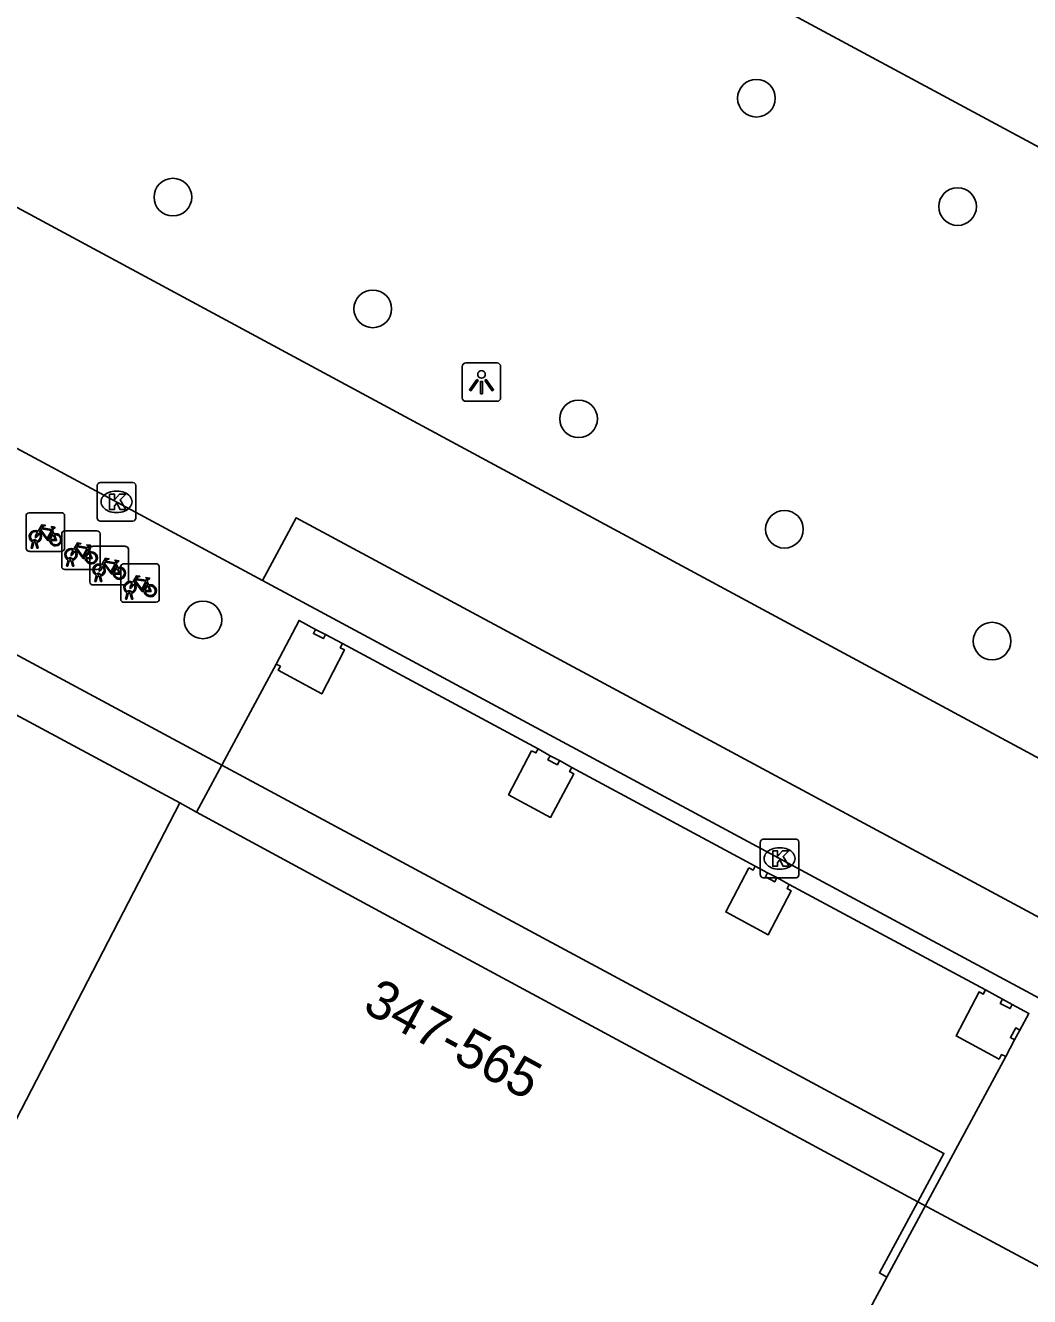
# Model space of a CAD drawing. Extents: x 159489 to 160304, y 383826 to 384530.
# Drawn here: x 159552.76 to 159578.83, y 384279.19 to 384312.2 of the extents above; entities that cross this region are included whole.
import ezdxf

# ---------------------------------------------------------------- set-up
doc = ezdxf.new("R2010")
doc.units = 0
for name, color, linetype in [('IMGEO_Boom', 7, 'Continuous'), ('IMGEO_Fietsenrek', 7, 'Continuous'), ('IMGEO_Kolk', 7, 'Continuous'), ('IMGEO_Lichtpunt', 7, 'Continuous'), ('IMGEO_Pand', 7, 'Continuous'), ('IMGEO_Pand_nummerreeks', 7, 'Continuous'), ('IMGEO_Pand_overbouw', 7, 'Continuous'), ('IMGEO_Rijbaan_lokaal_gesloten', 7, 'Continuous'), ('IMGEO_Voetgangersgebied_gesloten', 7, 'Continuous'), ('IMGEO_Voetpad_open', 7, 'Continuous')]:
    doc.layers.add(name, color=color, linetype=linetype)

msp = doc.modelspace()

# ---------------------------------------------------------------- linework, layer by layer
at = {"layer": 'IMGEO_Boom'}
for centre in [(159571.742, 384310.314), (159556.59, 384307.745), (159576.966, 384307.5), (159561.779, 384304.844), (159567.125, 384301.988), (159572.468, 384299.119), (159557.37, 384296.767), (159577.86, 384296.215)]:
    msp.add_circle(centre, 0.489, dxfattribs=at)
at = {"layer": 'IMGEO_Fietsenrek'}
for p, q in [((159552.779, 384298.622), (159552.779, 384299.463)), ((159552.779, 384299.463), (159552.779, 384298.622)), ((159552.854, 384299.547), (159553.695, 384299.547)), ((159553.695, 384299.547), (159552.854, 384299.547)), ((159553.779, 384299.472), (159553.779, 384298.631)), ((159553.779, 384298.631), (159553.779, 384299.472)), ((159553.466, 384299.096), (159553.502, 384299.001)), ((159553.777, 384299.077), (159554.618, 384299.077)), ((159554.618, 384299.077), (159553.777, 384299.077)), ((159552.906, 384298.631), (159552.945, 384298.791)), ((159552.975, 384298.779), (159552.94, 384298.631)), ((159553.017, 384298.803), (159553.016, 384298.807)), ((159553.058, 384298.631), (159553.024, 384298.773)), ((159553.048, 384298.814), (159553.049, 384298.807)), ((159553.056, 384298.777), (159553.091, 384298.631)), ((159553.702, 384298.152), (159553.702, 384298.993)), ((159553.702, 384298.993), (159553.702, 384298.152)), ((159554.702, 384299.002), (159554.702, 384298.161)), ((159554.702, 384298.161), (159554.702, 384299.002)), ((159553.704, 384298.547), (159552.863, 384298.547)), ((159552.863, 384298.547), (159553.704, 384298.547)), ((159552.94, 384298.631), (159552.906, 384298.631)), ((159553.091, 384298.631), (159553.058, 384298.631)), ((159554.389, 384298.626), (159554.425, 384298.531)), ((159554.433, 384297.752), (159554.433, 384298.593)), ((159554.433, 384298.593), (159554.433, 384297.752)), ((159554.508, 384298.677), (159555.349, 384298.677)), ((159555.349, 384298.677), (159554.508, 384298.677)), ((159555.433, 384298.602), (159555.433, 384297.761)), ((159555.433, 384297.761), (159555.433, 384298.602)), ((159554.627, 384298.077), (159553.786, 384298.077)), ((159553.786, 384298.077), (159554.627, 384298.077)), ((159553.829, 384298.161), (159553.868, 384298.321)), ((159553.863, 384298.161), (159553.829, 384298.161)), ((159553.898, 384298.309), (159553.863, 384298.161)), ((159553.94, 384298.333), (159553.939, 384298.337)), ((159553.981, 384298.161), (159553.947, 384298.303)), ((159553.971, 384298.344), (159553.972, 384298.337)), ((159553.979, 384298.307), (159554.014, 384298.161)), ((159554.014, 384298.161), (159553.981, 384298.161)), ((159555.12, 384298.226), (159555.156, 384298.131)), ((159555.234, 384297.299), (159555.234, 384298.14)), ((159555.234, 384298.14), (159555.234, 384297.299)), ((159555.309, 384298.224), (159556.15, 384298.224)), ((159556.15, 384298.224), (159555.309, 384298.224)), ((159556.234, 384298.149), (159556.234, 384297.308)), ((159556.234, 384297.308), (159556.234, 384298.149)), ((159554.56, 384297.761), (159554.599, 384297.921)), ((159554.594, 384297.761), (159554.56, 384297.761)), ((159554.629, 384297.909), (159554.594, 384297.761)), ((159554.671, 384297.933), (159554.67, 384297.937)), ((159554.712, 384297.761), (159554.678, 384297.903)), ((159554.702, 384297.944), (159554.703, 384297.937)), ((159554.71, 384297.907), (159554.745, 384297.761)), ((159554.745, 384297.761), (159554.712, 384297.761)), ((159555.921, 384297.773), (159555.957, 384297.678)), ((159555.358, 384297.677), (159554.517, 384297.677)), ((159554.517, 384297.677), (159555.358, 384297.677)), ((159555.361, 384297.308), (159555.4, 384297.468)), ((159555.43, 384297.456), (159555.395, 384297.308)), ((159555.472, 384297.48), (159555.471, 384297.484)), ((159555.513, 384297.308), (159555.479, 384297.45)), ((159555.503, 384297.491), (159555.504, 384297.484)), ((159555.511, 384297.454), (159555.546, 384297.308)), ((159556.159, 384297.224), (159555.318, 384297.224)), ((159555.318, 384297.224), (159556.159, 384297.224)), ((159555.395, 384297.308), (159555.361, 384297.308)), ((159555.546, 384297.308), (159555.513, 384297.308))]:
    msp.add_line(p, q, dxfattribs=at)
for points in [[(159553.092, 384299.073), (159553.187, 384299.237), (159553.273, 384299.223), (159553.275, 384299.214), (159553.219, 384299.203), (159553.192, 384299.158), (159553.448, 384299.117)], [(159553.388, 384298.829), (159553.338, 384298.829), (159553.147, 384299.08), (159553.128, 384299.048)], [(159553.435, 384299.092), (159553.178, 384299.133), (159553.161, 384299.104), (159553.328, 384298.884), (159553.435, 384299.092)], [(159553.483, 384298.994), (159553.453, 384299.071), (159553.344, 384298.853), (159553.387, 384298.853)], [(159553.448, 384299.117), (159553.473, 384299.166), (159553.467, 384299.17), (159553.444, 384299.174), (159553.432, 384299.181), (159553.431, 384299.184), (159553.433, 384299.189), (159553.528, 384299.174), (159553.53, 384299.164), (159553.52, 384299.151), (159553.508, 384299.145), (159553.494, 384299.151), (159553.466, 384299.096)], [(159553.113, 384299.021), (159553.061, 384298.931), (159553.021, 384298.906), (159553.022, 384298.953), (159553.077, 384299.047)], [(159553.417, 384298.853), (159553.537, 384298.852), (159553.493, 384298.966)], [(159553.513, 384298.973), (159553.568, 384298.828), (159553.418, 384298.828)], [(159554.015, 384298.603), (159554.11, 384298.767), (159554.196, 384298.753), (159554.198, 384298.744), (159554.142, 384298.733), (159554.115, 384298.688), (159554.371, 384298.647)], [(159554.036, 384298.551), (159553.984, 384298.461), (159553.944, 384298.436), (159553.945, 384298.483), (159554, 384298.577)], [(159554.311, 384298.359), (159554.261, 384298.359), (159554.07, 384298.61), (159554.051, 384298.578)], [(159554.358, 384298.622), (159554.101, 384298.663), (159554.084, 384298.634), (159554.251, 384298.414), (159554.358, 384298.622)], [(159554.406, 384298.524), (159554.376, 384298.601), (159554.267, 384298.383), (159554.31, 384298.383)], [(159554.34, 384298.383), (159554.46, 384298.382), (159554.416, 384298.496)], [(159554.436, 384298.503), (159554.491, 384298.358), (159554.341, 384298.358)], [(159554.371, 384298.647), (159554.396, 384298.696), (159554.39, 384298.7), (159554.367, 384298.704), (159554.355, 384298.711), (159554.354, 384298.714), (159554.356, 384298.719), (159554.451, 384298.704), (159554.453, 384298.694), (159554.443, 384298.681), (159554.431, 384298.675), (159554.417, 384298.681), (159554.389, 384298.626)], [(159554.767, 384298.151), (159554.715, 384298.061), (159554.675, 384298.036), (159554.676, 384298.083), (159554.731, 384298.177)], [(159554.746, 384298.203), (159554.841, 384298.367), (159554.927, 384298.353), (159554.929, 384298.344), (159554.873, 384298.333), (159554.846, 384298.288), (159555.102, 384298.247)], [(159555.042, 384297.959), (159554.992, 384297.959), (159554.801, 384298.21), (159554.782, 384298.178)], [(159555.089, 384298.222), (159554.832, 384298.263), (159554.815, 384298.234), (159554.982, 384298.014), (159555.089, 384298.222)], [(159555.137, 384298.124), (159555.107, 384298.201), (159554.998, 384297.983), (159555.041, 384297.983)], [(159555.071, 384297.983), (159555.191, 384297.982), (159555.147, 384298.096)], [(159555.167, 384298.103), (159555.222, 384297.958), (159555.072, 384297.958)], [(159555.102, 384298.247), (159555.127, 384298.296), (159555.121, 384298.3), (159555.098, 384298.304), (159555.086, 384298.311), (159555.085, 384298.314), (159555.087, 384298.319), (159555.182, 384298.304), (159555.184, 384298.294), (159555.174, 384298.281), (159555.162, 384298.275), (159555.148, 384298.281), (159555.12, 384298.226)], [(159555.547, 384297.75), (159555.642, 384297.914), (159555.728, 384297.9), (159555.73, 384297.891), (159555.674, 384297.88), (159555.647, 384297.835), (159555.903, 384297.794)], [(159555.843, 384297.506), (159555.793, 384297.506), (159555.602, 384297.757), (159555.583, 384297.725)], [(159555.89, 384297.769), (159555.633, 384297.81), (159555.616, 384297.781), (159555.783, 384297.561), (159555.89, 384297.769)], [(159555.938, 384297.671), (159555.908, 384297.748), (159555.799, 384297.53), (159555.842, 384297.53)], [(159555.903, 384297.794), (159555.928, 384297.843), (159555.922, 384297.847), (159555.899, 384297.851), (159555.887, 384297.858), (159555.886, 384297.861), (159555.888, 384297.866), (159555.983, 384297.851), (159555.985, 384297.841), (159555.975, 384297.828), (159555.963, 384297.822), (159555.949, 384297.828), (159555.921, 384297.773)], [(159555.568, 384297.698), (159555.516, 384297.608), (159555.476, 384297.583), (159555.477, 384297.63), (159555.532, 384297.724)], [(159555.872, 384297.53), (159555.992, 384297.529), (159555.948, 384297.643)], [(159555.968, 384297.65), (159556.023, 384297.505), (159555.873, 384297.505)]]:
    msp.add_lwpolyline(points, dxfattribs=at)
for centre, radius, start, end in [((159552.857, 384299.469), 0.0779, 92.4484, 184.2845), ((159552.857, 384299.469), 0.0779, 92.4484, 184.2845), ((159553.701, 384299.469), 0.0779, 2.4484, 94.2845), ((159553.701, 384299.469), 0.0779, 2.4484, 94.2845), ((159553.019, 384298.932), 0.159, 62.6766, 242.1369), ((159553.78, 384298.999), 0.0779, 92.4484, 184.2845), ((159553.78, 384298.999), 0.0779, 92.4484, 184.2845), ((159554.624, 384298.999), 0.0779, 2.4484, 94.2845), ((159554.624, 384298.999), 0.0779, 2.4484, 94.2845), ((159553.019, 384298.932), 0.129, 63.3192, 238.903), ((159552.999, 384298.803), 0.0499, 12.8025, 158.6934), ((159553.019, 384298.932), 0.159, 253.9967, 271.7867), ((159552.999, 384298.803), 0.0174, 12.8025, 163.4502), ((159553.019, 384298.932), 0.129, 253.415, 269.0204), ((159553.019, 384298.932), 0.129, 283.6043, 43.4302), ((159553.019, 384298.932), 0.159, 283.5766, 46.6042), ((159553.546, 384298.848), 0.159, 113.3408, 178.3217), ((159553.546, 384298.848), 0.159, 187.0065, 105.7708), ((159553.546, 384298.848), 0.129, 113.923, 177.9556), ((159553.546, 384298.848), 0.129, 188.6715, 104.5883), ((159552.857, 384298.625), 0.0779, 182.4484, 274.2845), ((159552.857, 384298.625), 0.0779, 182.4484, 274.2845), ((159553.701, 384298.625), 0.0779, 272.4484, 4.2845), ((159553.701, 384298.625), 0.0779, 272.4484, 4.2845), ((159553.942, 384298.462), 0.159, 62.6766, 242.1369), ((159553.942, 384298.462), 0.129, 63.3192, 238.903), ((159553.942, 384298.462), 0.129, 283.6043, 43.4302), ((159553.942, 384298.462), 0.159, 283.5766, 46.6042), ((159554.469, 384298.378), 0.159, 113.3408, 178.3217), ((159554.469, 384298.378), 0.159, 187.0065, 105.7708), ((159554.469, 384298.378), 0.129, 113.923, 177.9556), ((159554.469, 384298.378), 0.129, 188.6715, 104.5883), ((159554.511, 384298.599), 0.0779, 92.4484, 184.2845), ((159554.511, 384298.599), 0.0779, 92.4484, 184.2845), ((159555.355, 384298.599), 0.0779, 2.4484, 94.2845), ((159555.355, 384298.599), 0.0779, 2.4484, 94.2845), ((159553.78, 384298.155), 0.0779, 182.4484, 274.2845), ((159553.78, 384298.155), 0.0779, 182.4484, 274.2845), ((159553.922, 384298.333), 0.0499, 12.8025, 158.6934), ((159553.942, 384298.462), 0.159, 253.9967, 271.7867), ((159553.922, 384298.333), 0.0174, 12.8025, 163.4502), ((159553.942, 384298.462), 0.129, 253.415, 269.0204), ((159554.673, 384298.062), 0.159, 62.6766, 242.1369), ((159554.673, 384298.062), 0.129, 63.3192, 238.903), ((159554.624, 384298.155), 0.0779, 272.4484, 4.2845), ((159554.624, 384298.155), 0.0779, 272.4484, 4.2845), ((159554.673, 384298.062), 0.129, 283.6043, 43.4302), ((159554.673, 384298.062), 0.159, 283.5766, 46.6042), ((159555.2, 384297.978), 0.159, 113.3408, 178.3217), ((159555.2, 384297.978), 0.159, 187.0065, 105.7708), ((159555.2, 384297.978), 0.129, 113.923, 177.9556), ((159555.2, 384297.978), 0.129, 188.6715, 104.5883), ((159555.312, 384298.146), 0.0779, 92.4484, 184.2845), ((159555.312, 384298.146), 0.0779, 92.4484, 184.2845), ((159556.156, 384298.146), 0.0779, 2.4484, 94.2845), ((159556.156, 384298.146), 0.0779, 2.4484, 94.2845), ((159554.511, 384297.755), 0.0779, 182.4484, 274.2845), ((159554.511, 384297.755), 0.0779, 182.4484, 274.2845), ((159554.653, 384297.933), 0.0499, 12.8025, 158.6934), ((159554.673, 384298.062), 0.159, 253.9967, 271.7867), ((159554.653, 384297.933), 0.0174, 12.8025, 163.4502), ((159554.673, 384298.062), 0.129, 253.415, 269.0204), ((159555.474, 384297.609), 0.159, 62.6766, 242.1369), ((159555.355, 384297.755), 0.0779, 272.4484, 4.2845), ((159555.355, 384297.755), 0.0779, 272.4484, 4.2845), ((159555.474, 384297.609), 0.129, 63.3192, 238.903), ((159555.454, 384297.48), 0.0499, 12.8025, 158.6934), ((159555.474, 384297.609), 0.159, 253.9967, 271.7867), ((159555.454, 384297.48), 0.0174, 12.8025, 163.4502), ((159555.474, 384297.609), 0.129, 253.415, 269.0204), ((159555.474, 384297.609), 0.129, 283.6043, 43.4302), ((159555.474, 384297.609), 0.159, 283.5766, 46.6042), ((159556.001, 384297.525), 0.159, 113.3408, 178.3217), ((159556.001, 384297.525), 0.159, 187.0065, 105.7708), ((159556.001, 384297.525), 0.129, 113.923, 177.9556), ((159556.001, 384297.525), 0.129, 188.6715, 104.5883), ((159555.312, 384297.302), 0.0779, 182.4484, 274.2845), ((159555.312, 384297.302), 0.0779, 182.4484, 274.2845), ((159556.156, 384297.302), 0.0779, 272.4484, 4.2845), ((159556.156, 384297.302), 0.0779, 272.4484, 4.2845)]:
    msp.add_arc(centre, radius, start, end, dxfattribs=at)
at = {"layer": 'IMGEO_Kolk'}
for p, q in [((159554.626, 384299.407), (159554.626, 384300.259)), ((159554.701, 384300.333), (159555.553, 384300.333)), ((159555.114, 384300.113), (159555.139, 384300.113)), ((159555.627, 384300.259), (159555.627, 384299.407)), ((159555.137, 384299.553), (159555.112, 384299.553)), ((159555.553, 384299.333), (159554.701, 384299.333)), ((159571.843, 384290.145), (159571.843, 384290.997)), ((159571.918, 384291.071), (159572.77, 384291.071)), ((159572.331, 384290.851), (159572.356, 384290.851)), ((159572.844, 384290.997), (159572.844, 384290.145)), ((159572.354, 384290.291), (159572.329, 384290.291)), ((159572.77, 384290.071), (159571.918, 384290.071))]:
    msp.add_line(p, q, dxfattribs=at)
for points in [[(159554.626, 384299.407), (159554.626, 384300.259)], [(159554.701, 384300.333), (159555.553, 384300.333)], [(159555.627, 384300.259), (159555.627, 384299.407)], [(159554.947, 384300.033), (159555.07, 384300.033), (159555.07, 384299.882), (159555.2, 384300.033), (159555.364, 384300.033), (159555.218, 384299.882), (159555.371, 384299.633), (159555.219, 384299.633), (159555.134, 384299.797), (159555.07, 384299.73), (159555.07, 384299.633), (159554.947, 384299.633), (159554.947, 384300.033)], [(159555.553, 384299.333), (159554.701, 384299.333)], [(159571.843, 384290.145), (159571.843, 384290.997)], [(159571.918, 384291.071), (159572.77, 384291.071)], [(159572.844, 384290.997), (159572.844, 384290.145)], [(159572.164, 384290.771), (159572.287, 384290.771), (159572.287, 384290.62), (159572.417, 384290.771), (159572.581, 384290.771), (159572.435, 384290.62), (159572.588, 384290.371), (159572.436, 384290.371), (159572.351, 384290.535), (159572.287, 384290.468), (159572.287, 384290.371), (159572.164, 384290.371), (159572.164, 384290.771)], [(159572.77, 384290.071), (159571.918, 384290.071)]]:
    msp.add_lwpolyline(points, dxfattribs=at)
for centre, start, end in [((159554.703, 384300.257), 91.552, 178.448), ((159554.703, 384300.257), 91.552, 178.448), ((159555.551, 384300.257), 1.552, 88.448), ((159555.551, 384300.257), 1.552, 88.448), ((159554.703, 384299.409), 181.552, 268.448), ((159554.703, 384299.409), 181.552, 268.448), ((159555.551, 384299.409), 271.552, 358.448), ((159555.551, 384299.409), 271.552, 358.448), ((159571.92, 384290.995), 91.552, 178.448), ((159571.92, 384290.995), 91.552, 178.448), ((159572.768, 384290.995), 1.552, 88.448), ((159572.768, 384290.995), 1.552, 88.448), ((159571.92, 384290.147), 181.552, 268.448), ((159571.92, 384290.147), 181.552, 268.448), ((159572.768, 384290.147), 271.552, 358.448), ((159572.768, 384290.147), 271.552, 358.448)]:
    msp.add_arc(centre, 0.0765, start, end, dxfattribs=at)
for centre, major_axis, ratio, start_param, end_param in [((159555.113, 384299.833), (-0.387, 0.002), 0.722429, 4.712389, 7.853982), ((159555.138, 384299.833), (-0.39, 0.002), 0.717154, 1.570796, 4.712389), ((159572.33, 384290.571), (-0.387, 0.002), 0.722429, 4.712389, 7.853982), ((159572.355, 384290.571), (-0.39, 0.002), 0.717154, 1.570796, 4.712389)]:
    msp.add_ellipse(centre, major_axis=major_axis, ratio=ratio, start_param=start_param, end_param=end_param, dxfattribs=at)
at = {"layer": 'IMGEO_Lichtpunt'}
for p, q in [((159565.006, 384303.439), (159564.198, 384303.439)), ((159565.006, 384303.439), (159564.198, 384303.439)), ((159564.104, 384303.344), (159564.104, 384302.537)), ((159564.104, 384303.344), (159564.104, 384302.537)), ((159565.1, 384302.537), (159565.1, 384303.344)), ((159565.1, 384302.537), (159565.1, 384303.344)), ((159564.198, 384302.443), (159565.006, 384302.443)), ((159564.198, 384302.443), (159565.006, 384302.443))]:
    msp.add_line(p, q, dxfattribs=at)
for points in [[(159564.478, 384303.008), (159564.517, 384302.98), (159564.329, 384302.718), (159564.291, 384302.745), (159564.478, 384303.008)], [(159564.58, 384302.96), (159564.627, 384302.96), (159564.627, 384302.638), (159564.58, 384302.638), (159564.58, 384302.96)], [(159564.69, 384302.98), (159564.728, 384303.007), (159564.915, 384302.745), (159564.876, 384302.717), (159564.69, 384302.98)]]:
    msp.add_lwpolyline(points, dxfattribs=at)
msp.add_circle((159564.603, 384303.142), 0.0994, dxfattribs=at)
for centre, start, end in [((159564.198, 384303.344), 90, 180), ((159564.198, 384303.344), 90, 180), ((159565.006, 384303.344), 0, 90), ((159565.006, 384303.344), 0, 90), ((159564.198, 384302.537), 180, 270), ((159564.198, 384302.537), 180, 270), ((159565.006, 384302.537), 270, 0), ((159565.006, 384302.537), 270, 360)]:
    msp.add_arc(centre, 0.0946, start, end, dxfattribs=at)
at = {"layer": 'IMGEO_Pand'}
for points in [[(159527.484, 384307.756), (159556.766, 384292.015)], [(159559.382, 384295.564), (159559.275, 384295.619), (159559.868, 384296.753), (159560.296, 384296.519), (159560.239, 384296.411), (159560.498, 384296.28), (159560.556, 384296.388), (159560.994, 384296.151), (159560.936, 384296.043), (159561.044, 384295.985), (159560.456, 384294.845), (159559.324, 384295.457), (159559.382, 384295.564)], [(159565.904, 384293.366), (159566.015, 384293.31), (159566.072, 384293.416), (159566.382, 384293.24), (159566.327, 384293.131), (159566.576, 384293.004), (159566.63, 384293.113), (159566.946, 384292.937), (159566.89, 384292.829), (159566.999, 384292.769), (159566.395, 384291.637), (159565.308, 384292.224), (159565.904, 384293.366)], [(159556.766, 384292.015), (159545.068, 384269.391)], [(159556.766, 384292.015), (159557.204, 384291.777), (159563.611, 384288.299), (159575.933, 384281.657)], [(159571.543, 384290.325), (159571.654, 384290.27), (159571.711, 384290.375), (159572.031, 384290.202), (159571.975, 384290.09), (159572.218, 384289.961), (159572.274, 384290.073), (159572.594, 384289.895), (159572.536, 384289.787), (159572.645, 384289.73), (159572.049, 384288.588), (159570.947, 384289.184), (159571.543, 384290.325)], [(159577.69, 384287.156), (159578.134, 384286.918), (159578.074, 384286.808), (159578.327, 384286.674), (159578.384, 384286.782), (159578.819, 384286.547), (159578.582, 384286.113), (159578.477, 384286.17), (159578.339, 384285.92), (159578.446, 384285.864), (159578.215, 384285.424), (159578.109, 384285.479), (159578.044, 384285.36), (159576.926, 384285.964), (159577.522, 384287.106), (159577.633, 384287.05), (159577.69, 384287.156)], [(159554.827, 384264.14), (159556.176, 384266.653), (159565.449, 384261.675), (159575.127, 384279.7), (159574.935, 384279.809), (159575.933, 384281.657)]]:
    msp.add_lwpolyline(points, dxfattribs=at)
at = {"layer": 'IMGEO_Pand_overbouw'}
msp.add_lwpolyline([(159572.594, 384289.895), (159572.274, 384290.073), (159572.031, 384290.202), (159571.711, 384290.375), (159566.946, 384292.937), (159566.63, 384293.113), (159566.382, 384293.24), (159566.072, 384293.416), (159560.994, 384296.151), (159560.556, 384296.388), (159560.296, 384296.519), (159559.868, 384296.753), (159559.275, 384295.619), (159557.204, 384291.777), (159563.611, 384288.299), (159575.933, 384281.657), (159574.935, 384279.809), (159575.127, 384279.7), (159578.215, 384285.424), (159578.446, 384285.864), (159578.582, 384286.113), (159578.819, 384286.547), (159578.384, 384286.782), (159578.134, 384286.918), (159577.69, 384287.156)], close=True, dxfattribs=at)
at = {"layer": 'IMGEO_Rijbaan_lokaal_gesloten'}
for points in [[(159582.424, 384291.365), (159546.562, 384310.695), (159542.586, 384312.826), (159525.025, 384322.248), (159521.207, 384324.29)], [(159549.449, 384302.878), (159558.914, 384297.788)], [(159558.914, 384297.788), (159559.789, 384299.414), (159596.815, 384279.502), (159606.884, 384274.087), (159606.009, 384272.461)]]:
    msp.add_lwpolyline(points, dxfattribs=at)
at = {"layer": 'IMGEO_Voetgangersgebied_gesloten'}
msp.add_lwpolyline([(159535.907, 384332.261), (159543.023, 384328.421), (159557.045, 384320.898), (159580.231, 384308.416)], dxfattribs=at)
at = {"layer": 'IMGEO_Voetpad_open'}
for points in [[(159526.055, 384310.099), (159576.611, 384282.913), (159575.933, 384281.657)], [(159558.914, 384297.788), (159595.94, 384277.876), (159606.009, 384272.461)], [(159575.933, 384281.657), (159590.223, 384274)]]:
    msp.add_lwpolyline(points, dxfattribs=at)

# ---------------------------------------------------------------- texts
at = {"layer": 'IMGEO_Pand_nummerreeks'}
msp.add_text('347-565', height=1, rotation=331.4782, dxfattribs=at).set_placement((159561.48, 384286.62))

doc.saveas('drawing.dxf')
